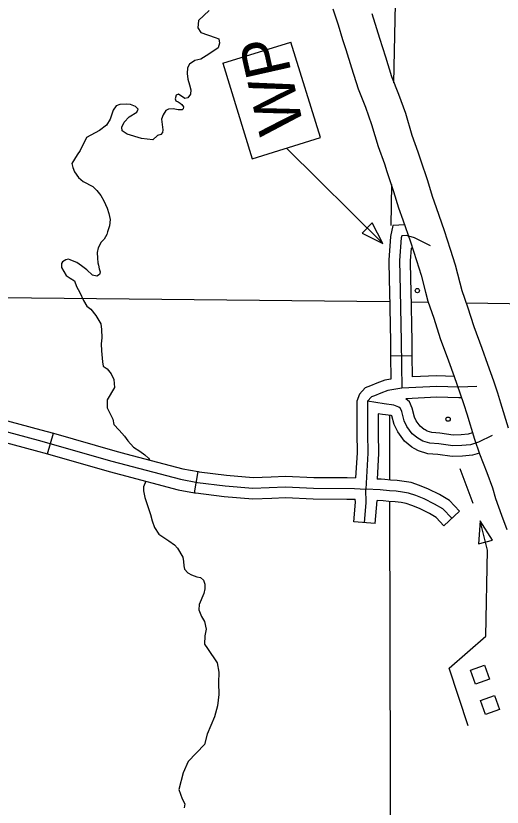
# Model space of a CAD drawing. Extents: x 61396 to 64680, y 55472 to 57605.
# Drawn here: x 62536.1 to 62642.3, y 56426.3 to 56599.4 of the extents above; entities that cross this region are included whole.
import ezdxf

# ---------------------------------------------------------------- set-up
doc = ezdxf.new("R2010")
doc.units = 0
for name, color, linetype in [('15', 7, 'Continuous'), ('35', 7, 'Continuous'), ('45', 7, 'Continuous'), ('5', 7, 'Continuous'), ('56', 7, 'Continuous'), ('57', 7, 'Continuous')]:
    doc.layers.add(name, color=color, linetype=linetype)

msp = doc.modelspace()

# ---------------------------------------------------------------- linework, layer by layer
at = {"layer": '15'}
for points in [[(62605.33, 56600.9), (62606.5, 56597.47), (62607.48, 56594.26), (62608.17, 56592.06), (62609.45, 56588.05), (62610.87, 56583.43), (62612.48, 56579.42), (62613.82, 56575.62), (62615.23, 56570.8), (62616.63, 56567.04), (62617.17, 56565.38), (62618.63, 56560.97), (62619.69, 56557.44), (62620.66, 56554.79), (62622.32, 56549.97), (62623.61, 56545.87), (62624.67, 56542.66), (62625.61, 56538.95), (62626.13, 56536.99), (62627.44, 56533.25), (62628.83, 56528.85), (62630.65, 56523.98), (62631.85, 56520.52), (62633.12, 56516.98), (62633.95, 56514.43), (62634.63, 56512.33), (62636.32, 56506.8), (62637.41, 56503.63), (62639.02, 56499.49), (62640.23, 56496.19), (62640.89, 56493.8), (62642.19, 56490.21), (62643.39, 56487.08)], [(62643.75, 56509.21), (62642.08, 56514.67), (62641.38, 56516.84), (62640.51, 56519.51), (62639.22, 56523.12), (62638, 56526.63), (62636.22, 56531.39), (62634.85, 56535.71), (62633.61, 56539.28), (62633.17, 56540.91), (62632.17, 56544.84), (62631.05, 56548.27), (62629.74, 56552.41), (62628.02, 56557.41), (62627.1, 56559.92), (62626.08, 56563.32), (62624.59, 56567.82), (62624, 56569.62), (62622.65, 56573.26), (62621.26, 56578.01), (62619.8, 56582.18), (62618.24, 56586.04), (62616.9, 56590.38), (62615.62, 56594.42), (62614.94, 56596.58), (62613.93, 56599.87)]]:
    msp.add_lwpolyline(points, dxfattribs=at)
at = {"layer": '35'}
for points in [[(62578.29, 56600.6), (62575.97, 56598.39), (62575.82, 56596.75), (62576.53, 56595.74), (62579.6, 56594.69), (62580.46, 56594.35), (62580.59, 56593.42), (62580.28, 56592.41), (62578.25, 56590.99), (62576.53, 56589.94), (62575.19, 56589.6), (62574.03, 56588.82), (62573.58, 56588), (62573.5, 56586.76), (62573.65, 56585.57), (62574.03, 56584.3), (62574.33, 56583.25), (62574.25, 56582.24), (62573.65, 56581.49), (62573.02, 56581.3), (62571.63, 56582.24), (62571.08, 56582.02), (62570.9, 56581.24), (62571.06, 56580.78), (62571.53, 56580.56), (62571.97, 56580.28), (62572.32, 56580), (62572.7, 56579.48), (62572.61, 56579.03), (62572.42, 56578.81), (62571.55, 56578.84), (62570.45, 56579.04), (62569.42, 56578.97), (62568.86, 56578.68), (62568.3, 56577.76), (62567.94, 56576.79), (62568.04, 56575.6), (62568.21, 56574.47), (62568.15, 56573.9), (62567.78, 56573.43), (62567.03, 56573.26), (62565.98, 56572.28), (62563.5, 56572.54), (62560.4, 56573.49)], [(62560.4, 56573.49), (62559.32, 56574.24), (62559.22, 56575.03), (62559.78, 56576.17), (62560.86, 56577.31), (62562.49, 56578.33), (62562.78, 56579.01), (62562.2, 56579.6), (62561.15, 56579.99), (62560.24, 56580.12), (62558.8, 56580.02), (62557.98, 56579.7), (62557.33, 56578.75), (62556.71, 56576.82), (62555.86, 56575.52), (62554.39, 56574.31), (62551.48, 56572.77), (62550.13, 56569.94), (62549.51, 56569), (62548.34, 56567.1), (62548.5, 56566.25), (62548.86, 56565.28), (62549.78, 56564.04), (62550.79, 56563.2), (62552.89, 56562.1), (62552.96, 56561.97), (62553.75, 56561.19), (62554.66, 56560.11), (62555.33, 56558.95), (62556.01, 56557.36), (62556.42, 56556.2), (62556.69, 56554.89), (62556.57, 56553.47), (62556.09, 56552.15), (62555.93, 56551.58), (62555.35, 56550.57), (62554.73, 56549.91), (62554.08, 56548.68), (62553.84, 56547.61), (62553.92, 56546.41), (62553.96, 56545.35), (62554.12, 56544.88), (62554.31, 56544.06), (62554.51, 56543.38), (62554.42, 56543.06), (62554.33, 56542.84), (62553.74, 56542.43), (62552.86, 56542.67), (62551.59, 56543.82), (62550.4, 56544.74), (62549.39, 56545.42), (62548.79, 56545.7), (62547.91, 56546.07), (62547.6, 56546.16), (62546.97, 56546.06), (62546.29, 56545.61), (62546.07, 56545.26), (62546.05, 56544.38), (62547.07, 56542.64), (62547.92, 56542.05), (62548.86, 56541.43), (62549.34, 56540.21), (62550.08, 56538.87), (62550.84, 56537.12), (62551.61, 56535.91), (62552.43, 56535.22), (62553.57, 56533.86), (62554.62, 56532.02), (62554.78, 56530.79), (62554.83, 56528.97), (62554.69, 56527.65), (62554.78, 56526.15), (62555.02, 56523.71), (62555.19, 56522.78), (62556.04, 56522.17), (62556.93, 56521.11), (62557.5, 56519.86), (62557.64, 56518.12)], [(62557.64, 56518.12), (62556, 56515.38), (62556.05, 56513.64), (62557.25, 56511.2), (62557.51, 56509.99), (62558.67, 56508.77), (62559.84, 56507.45), (62560.56, 56506.44), (62561.79, 56505.07), (62563.14, 56504.17), (62564.29, 56503.42), (62565.03, 56502.66), (62565.25, 56502.26)], [(62564.5, 56497.62), (62563.97, 56496.38), (62563.97, 56495.54), (62564.23, 56494.04), (62565.06, 56491.65), (62565.5, 56490.37), (62565.83, 56488.97), (62566.4, 56487.52), (62567.32, 56486.07), (62567.77, 56485.74), (62569.5, 56484.6), (62570.72, 56483.7), (62571.37, 56483), (62572.55, 56481.03), (62572.68, 56480.09), (62572.8, 56479.09), (62572.95, 56478.37), (62573.63, 56477.58), (62574.46, 56477.13), (62575.6, 56476.73), (62576.45, 56476.57), (62577.06, 56475.96), (62577.4, 56475.09), (62577.4, 56474.09), (62577.15, 56473.08), (62576.13, 56470.63), (62576.07, 56469.5), (62576.65, 56468.01), (62577.31, 56466.93), (62577.7, 56465.28), (62577.37, 56463.83), (62577.33, 56461.97), (62577.96, 56461.05), (62580.06, 56457.92), (62580.43, 56455.86), (62580.35, 56453.5), (62580.4, 56450.96), (62580.13, 56448.47), (62579.51, 56446.07), (62577.89, 56442.26), (62577.3, 56440.02), (62573.76, 56436.34), (62572.67, 56433.8), (62571.72, 56430.22), (62572.42, 56428.18), (62573.02, 56427.09), (62572.87, 56426.19)]]:
    msp.add_lwpolyline(points, dxfattribs=at)
at = {"layer": '45'}
for p, q in [((62617.96, 56525.06), (62622.64, 56525.12)), ((62542.98, 56503.59), (62544.27, 56508.1)), ((62575.1, 56495.11), (62575.94, 56499.72)), ((62633.02, 56491.1), (62629.62, 56487.89)), ((62614.62, 56488.35), (62609.94, 56488.71))]:
    msp.add_line(p, q, dxfattribs=at)
for points in [[(62621.05, 56553.66), (62618.46, 56553.55), (62617.98, 56551.15), (62617.55, 56545.95), (62617.64, 56541.54)], [(62626.69, 56549.1), (62623.22, 56550.87), (62621.46, 56551.33), (62620.4, 56551.28), (62620.31, 56550.82), (62619.89, 56545.88), (62620.03, 56539.32), (62620.26, 56528.14), (62620.39, 56517.96)], [(62622.8, 56548.45), (62622.48, 56548.62), (62622.24, 56545.81), (62622.33, 56541.64)], [(62617.64, 56541.54), (62617.69, 56539.27), (62617.92, 56528.1), (62617.96, 56525.06)], [(62622.33, 56541.64), (62622.37, 56539.37), (62622.61, 56528.18), (62622.64, 56525.12)], [(62617.96, 56525.06), (62618.02, 56519.95)], [(62622.64, 56525.12), (62622.7, 56520.42)], [(62618.02, 56519.95), (62616.74, 56519.74), (62614.96, 56519.08), (62613.54, 56518.5), (62612.4, 56518.04), (62611.18, 56516.66)], [(62631.84, 56520.55), (62628.05, 56520.7), (62622.7, 56520.42)], [(62636.79, 56518.32), (62632.89, 56518.16), (62628.07, 56518.35), (62620.39, 56517.96)], [(62512.82, 56517.13), (62517.38, 56514.65), (62523.73, 56511.33), (62529.79, 56509.55), (62540.95, 56506.61), (62557.07, 56502), (62572.03, 56498.05), (62575.79, 56497.36), (62581.83, 56496.62), (62587.88, 56496.11), (62595, 56496.39), (62601.1, 56496.11), (62610.05, 56496.05), (62612.53, 56495.9)], [(62611.18, 56516.66), (62610.59, 56515.11), (62610.59, 56512.95), (62610.59, 56508.11), (62610.65, 56503.8), (62610.33, 56498.39)], [(62620.39, 56517.96), (62617.34, 56517.47), (62615.82, 56516.89), (62614.42, 56516.32), (62613.78, 56516.07), (62612.93, 56515.11)], [(62612.93, 56515.11), (62612.93, 56512.95), (62612.93, 56508.13), (62612.99, 56503.75), (62612.53, 56495.9)], [(62640.16, 56507.65), (62637.19, 56506.14), (62635.39, 56505.61), (62633.53, 56505.45), (62631.54, 56505.35), (62628.51, 56505.76), (62626.56, 56505.92), (62625.01, 56506.39), (62623.94, 56507.03), (62622.71, 56508), (62621.54, 56509.61), (62620.94, 56510.81), (62620.44, 56512.86), (62620.15, 56513.52), (62619.78, 56513.84), (62618.64, 56514.25), (62616.56, 56514.53), (62612.93, 56515.11)], [(62633.49, 56515.84), (62632.89, 56515.82), (62628.08, 56516.01), (62621.26, 56515.65)], [(62625.51, 56508.82), (62625.27, 56508.96), (62624.42, 56509.64), (62623.55, 56510.83), (62623.16, 56511.62), (62622.67, 56513.61), (62622.09, 56514.96), (62621.26, 56515.65)], [(62528.36, 56512.41), (62530.42, 56511.81), (62541.57, 56508.87), (62544.27, 56508.1)], [(62615.27, 56512.36), (62615.27, 56508.15), (62615.34, 56503.69), (62615.01, 56498.1)], [(62623.13, 56504.78), (62622.61, 56505.09), (62621, 56506.37), (62619.53, 56508.39), (62618.73, 56510), (62618.26, 56511.89), (62618.08, 56511.96), (62616.22, 56512.21), (62615.27, 56512.36)], [(62527.04, 56507.91), (62529.16, 56507.29), (62540.33, 56504.35), (62542.98, 56503.59)], [(62544.27, 56508.1), (62557.69, 56504.26), (62560.1, 56503.62)], [(62635.89, 56508.2), (62634.95, 56507.92), (62633.37, 56507.79), (62631.64, 56507.7), (62628.76, 56508.09), (62627, 56508.24), (62625.96, 56508.55), (62625.51, 56508.82)], [(62637.37, 56503.75), (62635.83, 56503.29), (62633.68, 56503.11), (62631.44, 56503), (62628.26, 56503.43), (62626.11, 56503.61), (62624.06, 56504.23), (62623.13, 56504.78)], [(62542.98, 56503.59), (62556.44, 56499.74), (62558.91, 56499.09)], [(62560.1, 56503.62), (62572.54, 56500.34), (62575.94, 56499.72)], [(62558.91, 56499.09), (62571.52, 56495.76), (62575.1, 56495.11)], [(62575.94, 56499.72), (62576.14, 56499.68), (62582.08, 56498.95), (62587.93, 56498.46), (62591.85, 56498.61)], [(62591.85, 56498.61), (62595.01, 56498.74), (62601.17, 56498.45), (62608.45, 56498.4)], [(62608.45, 56498.4), (62610.33, 56498.39)], [(62616.73, 56497.97), (62615.87, 56498.05), (62615.01, 56498.1)], [(62633.02, 56491.1), (62630.86, 56493.4), (62628.68, 56494.69), (62626.24, 56495.91), (62624.27, 56496.71), (62622.49, 56497.3), (62620.94, 56497.57), (62619.41, 56497.76), (62617.94, 56497.87), (62616.73, 56497.97)], [(62612.28, 56488.53), (62612.62, 56492.97), (62612.53, 56495.9)], [(62631.32, 56489.5), (62629.38, 56491.55), (62627.56, 56492.63), (62625.28, 56493.77), (62623.45, 56494.51), (62621.91, 56495.02), (62620.6, 56495.25), (62619.18, 56495.42), (62617.75, 56495.54), (62615.7, 56495.71), (62612.53, 56495.9)], [(62575.1, 56495.11), (62575.44, 56495.04), (62581.59, 56494.29), (62587.83, 56493.76), (62592.04, 56493.93)], [(62592.04, 56493.93), (62595, 56494.05), (62601.04, 56493.76), (62608.42, 56493.72)], [(62608.42, 56493.72), (62610.25, 56493.71)], [(62609.94, 56488.71), (62610.27, 56493.03), (62610.25, 56493.71)], [(62614.62, 56488.35), (62615.01, 56493.41)], [(62616.34, 56493.3), (62615.01, 56493.41)], [(62629.62, 56487.89), (62627.9, 56489.7), (62626.43, 56490.57), (62624.31, 56491.63), (62622.64, 56492.31), (62621.34, 56492.75), (62620.26, 56492.93), (62618.94, 56493.09), (62617.56, 56493.2), (62616.34, 56493.3)]]:
    msp.add_lwpolyline(points, dxfattribs=at)
at = {"layer": '5'}
for points in [[(62620.68, 56685.27), (62618.63, 56584.77)], [(62618.17, 56562.48), (62617.99, 56553.52)], [(62617.74, 56536.84), (62468.35, 56538.36)], [(62626.23, 56536.71), (62622.43, 56536.77)], [(62695.2, 56535.64), (62634.58, 56536.58)], [(62617.7, 56511.94), (62617.73, 56497.89)], [(62617.74, 56493.19), (62618, 56371.46)]]:
    msp.add_lwpolyline(points, dxfattribs=at)
at = {"layer": '56'}
for points in [[(62633.13, 56500.4), (62635.94, 56492.79)], [(62634.94, 56444.11), (62630.73, 56456.73)]]:
    msp.add_lwpolyline(points, dxfattribs=at)
for points in [[(62636.5, 56453.2), (62635.41, 56456.26), (62638.48, 56457.36), (62639.58, 56454.3)], [(62638.71, 56446.59), (62637.61, 56449.65), (62640.69, 56450.75), (62641.78, 56447.69)]]:
    msp.add_lwpolyline(points, close=True, dxfattribs=at)
at = {"layer": '57'}
for p, q in [((62581.27, 56589.04), (62596.19, 56593.66)), ((62602.66, 56572.76), (62596.19, 56593.66)), ((62581.27, 56589.04), (62587.74, 56568.14)), ((62587.74, 56568.14), (62602.66, 56572.76))]:
    msp.add_line(p, q, dxfattribs=at)
for points in [[(62595.2, 56570.45), (62616.24, 56549.61)], [(62630.73, 56456.73), (62638.74, 56463.74), (62639.14, 56482.57), (62637.54, 56488.98)]]:
    msp.add_lwpolyline(points, dxfattribs=at)
for points in [[(62613.97, 56554.11), (62611.72, 56551.84), (62616.24, 56549.61)], [(62637.16, 56483.95), (62640.25, 56484.73), (62637.54, 56488.98)]]:
    msp.add_lwpolyline(points, close=True, dxfattribs=at)
for centre in [(62623.81, 56539.3), (62630.53, 56511.19)]:
    msp.add_circle(centre, 0.469, dxfattribs=at)

# ---------------------------------------------------------------- texts
msp.add_text('WP', height=9.9, rotation=102.6823, dxfattribs=at).set_placement((62599.08, 56574.89))

doc.saveas('drawing.dxf')
